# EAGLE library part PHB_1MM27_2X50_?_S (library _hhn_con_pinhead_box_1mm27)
Pin Header Box-Type, 1.27mm/0.5"/50mil Pitch, 2x50 Circuits, single gates in schematic Note: see library description for an important note about THT-version
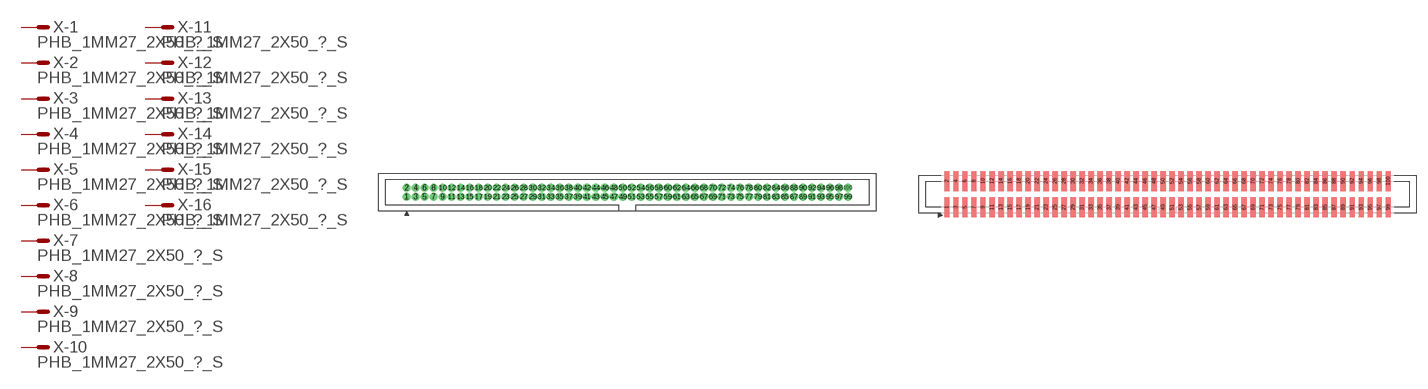
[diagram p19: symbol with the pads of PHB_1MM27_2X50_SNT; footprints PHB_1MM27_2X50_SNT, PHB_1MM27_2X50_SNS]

Designator prefix X; gates -1=M -2=M -3=M -4=M -5=M -6=M -7=M -8=M -9=M -10=M -11=M -12=M -13=M -14=M -15=M -16=M -17=M -18=M -19=M -20=M -21=M -22=M -23=M -24=M -25=M -26=M -27=M -28=M -29=M -30=M -31=M -32=M -33=M -34=M -35=M -36=M -37=M -38=M -39=M -40=M -41=M -42=M -43=M -44=M -45=M -46=M -47=M -48=M -49=M -50=M -51=M -52=M -53=M -54=M -55=M -56=M -57=M -58=M -59=M -60=M -61=M -62=M -63=M -64=M -65=M -66=M -67=M -68=M -69=M -70=M -71=M -72=M -73=M -74=M -75=M -76=M -77=M -78=M -79=M -80=M -81=M -82=M -83=M -84=M -85=M -86=M -87=M -88=M -89=M -90=M -91=M -92=M -93=M -94=M -95=M -96=M -97=M -98=M -99=M -100=M

## PHB_1MM27_2X50_SNT_S  [PHB_1MM27_2X50_SNT]
1  -1:S  pas
2  -2:S  pas
3  -3:S  pas
4  -4:S  pas
5  -5:S  pas
6  -6:S  pas
7  -7:S  pas
8  -8:S  pas
9  -9:S  pas
10  -10:S  pas
11  -11:S  pas
12  -12:S  pas
13  -13:S  pas
14  -14:S  pas
15  -15:S  pas
16  -16:S  pas
17  -17:S  pas
18  -18:S  pas
19  -19:S  pas
20  -20:S  pas
21  -21:S  pas
22  -22:S  pas
23  -23:S  pas
24  -24:S  pas
25  -25:S  pas
26  -26:S  pas
27  -27:S  pas
28  -28:S  pas
29  -29:S  pas
30  -30:S  pas
31  -31:S  pas
32  -32:S  pas
33  -33:S  pas
34  -34:S  pas
35  -35:S  pas
36  -36:S  pas
37  -37:S  pas
38  -38:S  pas
39  -39:S  pas
40  -40:S  pas
41  -41:S  pas
42  -42:S  pas
43  -43:S  pas
44  -44:S  pas
45  -45:S  pas
46  -46:S  pas
47  -47:S  pas
48  -48:S  pas
49  -49:S  pas
50  -50:S  pas
51  -51:S  pas
52  -52:S  pas
53  -53:S  pas
54  -54:S  pas
55  -55:S  pas
56  -56:S  pas
57  -57:S  pas
58  -58:S  pas
59  -59:S  pas
60  -60:S  pas
61  -61:S  pas
62  -62:S  pas
63  -63:S  pas
64  -64:S  pas
65  -65:S  pas
66  -66:S  pas
67  -67:S  pas
68  -68:S  pas
69  -69:S  pas
70  -70:S  pas
71  -71:S  pas
72  -72:S  pas
73  -73:S  pas
74  -74:S  pas
75  -75:S  pas
76  -76:S  pas
77  -77:S  pas
78  -78:S  pas
79  -79:S  pas
80  -80:S  pas
81  -81:S  pas
82  -82:S  pas
83  -83:S  pas
84  -84:S  pas
85  -85:S  pas
86  -86:S  pas
87  -87:S  pas
88  -88:S  pas
89  -89:S  pas
90  -90:S  pas
91  -91:S  pas
92  -92:S  pas
93  -93:S  pas
94  -94:S  pas
95  -95:S  pas
96  -96:S  pas
97  -97:S  pas
98  -98:S  pas
99  -99:S  pas
100  -100:S  pas

## PHB_1MM27_2X50_SNS_S  [PHB_1MM27_2X50_SNS]
Pads as for PHB_1MM27_2X50_SNT

## Footprint PHB_1MM27_2X50_SNT (pad centres in mm)
Pin Header Box-Type, 1.27mm Pitch, 2x50 circuits, Straight, No Locking, THT Important Note: Diameter in this lbr is set to a specific value (NOT 'auto' = 0), this is ignored by actual eagle versions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
drill 0.65 pad 1 round: 1 -31.115,-0.635; 2 -31.115,0.635; 3 -29.845,-0.635; 4 -29.845,0.635; 5 -28.575,-0.635; 6 -28.575,0.635; 7 -27.305,-0.635; 8 -27.305,0.635; 9 -26.035,-0.635; 10 -26.035,0.635; 11 -24.765,-0.635; 12 -24.765,0.635; 13 -23.495,-0.635; 14 -23.495,0.635; 15 -22.225,-0.635; 16 -22.225,0.635; 17 -20.955,-0.635; 18 -20.955,0.635; 19 -19.685,-0.635; 20 -19.685,0.635; 21 -18.415,-0.635; 22 -18.415,0.635; 23 -17.145,-0.635; 24 -17.145,0.635; 25 -15.875,-0.635; 26 -15.875,0.635; 27 -14.605,-0.635; 28 -14.605,0.635; 29 -13.335,-0.635; 30 -13.335,0.635; 31 -12.065,-0.635; 32 -12.065,0.635; 33 -10.795,-0.635; 34 -10.795,0.635; 35 -9.525,-0.635; 36 -9.525,0.635; 37 -8.255,-0.635; 38 -8.255,0.635; 39 -6.985,-0.635; 40 -6.985,0.635; 41 -5.715,-0.635; 42 -5.715,0.635; 43 -4.445,-0.635; 44 -4.445,0.635; 45 -3.175,-0.635; 46 -3.175,0.635; 47 -1.905,-0.635; 48 -1.905,0.635; 49 -0.635,-0.635; 50 -0.635,0.635; 51 0.635,-0.635; 52 0.635,0.635; 53 1.905,-0.635; 54 1.905,0.635; 55 3.175,-0.635; 56 3.175,0.635; 57 4.445,-0.635; 58 4.445,0.635; 59 5.715,-0.635; 60 5.715,0.635; 61 6.985,-0.635; 62 6.985,0.635; 63 8.255,-0.635; 64 8.255,0.635; 65 9.525,-0.635; 66 9.525,0.635; 67 10.795,-0.635; 68 10.795,0.635; 69 12.065,-0.635; 70 12.065,0.635; 71 13.335,-0.635; 72 13.335,0.635; 73 14.605,-0.635; 74 14.605,0.635; 75 15.875,-0.635; 76 15.875,0.635; 77 17.145,-0.635; 78 17.145,0.635; 79 18.415,-0.635; 80 18.415,0.635; 81 19.685,-0.635; 82 19.685,0.635; 83 20.955,-0.635; 84 20.955,0.635; 85 22.225,-0.635; 86 22.225,0.635; 87 23.495,-0.635; 88 23.495,0.635; 89 24.765,-0.635; 90 24.765,0.635; 91 26.035,-0.635; 92 26.035,0.635; 93 27.305,-0.635; 94 27.305,0.635; 95 28.575,-0.635; 96 28.575,0.635; 97 29.845,-0.635; 98 29.845,0.635; 99 31.115,-0.635; 100 31.115,0.635

## Footprint PHB_1MM27_2X50_SNS (pad centres in mm)
Pin Header Box-Type, 1.27mm Pitch, 2x50 circuits, Straight, No Locking, SMT
smd 0.76 x 2.8: 1 -31.115,-1.85; 2 -31.115,1.85; 3 -29.845,-1.85; 4 -29.845,1.85; 5 -28.575,-1.85; 6 -28.575,1.85; 7 -27.305,-1.85; 8 -27.305,1.85; 9 -26.035,-1.85; 10 -26.035,1.85; 11 -24.765,-1.85; 12 -24.765,1.85; 13 -23.495,-1.85; 14 -23.495,1.85; 15 -22.225,-1.85; 16 -22.225,1.85; 17 -20.955,-1.85; 18 -20.955,1.85; 19 -19.685,-1.85; 20 -19.685,1.85; 21 -18.415,-1.85; 22 -18.415,1.85; 23 -17.145,-1.85; 24 -17.145,1.85; 25 -15.875,-1.85; 26 -15.875,1.85; 27 -14.605,-1.85; 28 -14.605,1.85; 29 -13.335,-1.85; 30 -13.335,1.85; 31 -12.065,-1.85; 32 -12.065,1.85; 33 -10.795,-1.85; 34 -10.795,1.85; 35 -9.525,-1.85; 36 -9.525,1.85; 37 -8.255,-1.85; 38 -8.255,1.85; 39 -6.985,-1.85; 40 -6.985,1.85; 41 -5.715,-1.85; 42 -5.715,1.85; 43 -4.445,-1.85; 44 -4.445,1.85; 45 -3.175,-1.85; 46 -3.175,1.85; 47 -1.905,-1.85; 48 -1.905,1.85; 49 -0.635,-1.85; 50 -0.635,1.85; 51 0.635,-1.85; 52 0.635,1.85; 53 1.905,-1.85; 54 1.905,1.85; 55 3.175,-1.85; 56 3.175,1.85; 57 4.445,-1.85; 58 4.445,1.85; 59 5.715,-1.85; 60 5.715,1.85; 61 6.985,-1.85; 62 6.985,1.85; 63 8.255,-1.85; 64 8.255,1.85; 65 9.525,-1.85; 66 9.525,1.85; 67 10.795,-1.85; 68 10.795,1.85; 69 12.065,-1.85; 70 12.065,1.85; 71 13.335,-1.85; 72 13.335,1.85; 73 14.605,-1.85; 74 14.605,1.85; 75 15.875,-1.85; 76 15.875,1.85; 77 17.145,-1.85; 78 17.145,1.85; 79 18.415,-1.85; 80 18.415,1.85; 81 19.685,-1.85; 82 19.685,1.85; 83 20.955,-1.85; 84 20.955,1.85; 85 22.225,-1.85; 86 22.225,1.85; 87 23.495,-1.85; 88 23.495,1.85; 89 24.765,-1.85; 90 24.765,1.85; 91 26.035,-1.85; 92 26.035,1.85; 93 27.305,-1.85; 94 27.305,1.85; 95 28.575,-1.85; 96 28.575,1.85; 97 29.845,-1.85; 98 29.845,1.85; 99 31.115,-1.85; 100 31.115,1.85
